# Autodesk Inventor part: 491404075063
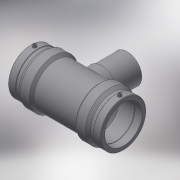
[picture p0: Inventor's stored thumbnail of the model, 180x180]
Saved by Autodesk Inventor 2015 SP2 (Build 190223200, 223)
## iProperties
Created: 2017-06
Part Number: 491404075063
Material: Generic
Description: PLASSON REDUCING TEE 75x63x75
Document SubType Name: Modeling
Designer: KIM
Mass: 591.776 g
Surface Area: 1368.9 cm^2
Volume: 591.776 cm^3
Density: 1 g/cm^3
Appearance: Default
Author: KIM
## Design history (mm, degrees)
derived "491404.ipt"
feature "Solid1::491404.ipt"
tag "TaggingFeature1"
body "Solid1"
other parameters: "d0" = 196, "d1" = 75, "d2" = 96, "d3" = 63, "d4" = 39.2, "d5" = 86.4, "d6" = 71.25, "d7" = 75, "d8" = 168 deg, "d10" = 25.2, "d11" = 8.4, "d13" = 196, "d14" = 17.6296, "d17" = 67.5, "d18" = 75, "d19" = 3.52592, "d20" = 168 deg, "d22" = 89.28, "d23" = 96, "d25" = 135 deg, "d26" = 137.2, "d29" = 62, "d30" = 15, "d31" = 78.4, "d34" = 5 deg, "d35" = 15, "d39" = 5 deg, "d41" = 4, "d42" = 14, "d43" = 0, "d45" = 4, "d46" = 6, "d47" = 0, "d48" = -122, "d49" = 63, "d51" = 0, "d52" = 50.4, "d54" = 0, "d55" = 86.4, "d56" = 96, "d57" = 68.6, "d58" = 135 deg, "d59" = 63, "d60" = 63, "d61" = 135 deg, "d62" = 122, "d72" = 89.18, "d73" = 44.59, "d74" = -122, "d75" = 66.15, "d77" = 0, "d78" = 50.4, "d80" = 0, "d81" = 63, "d82" = 74, "d83" = 0, "d84" = 3, "d85" = 0, "d86" = 21, "d87" = 87.4944, "d88" = 8.4, "d89" = 3, "d90" = 0, "d_" = 75, "L_" = 196, "L_1" = 63, "D_" = 96, "A_" = 62, "d_2" = 12, "H_" = 122, "d_1" = 63
